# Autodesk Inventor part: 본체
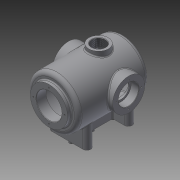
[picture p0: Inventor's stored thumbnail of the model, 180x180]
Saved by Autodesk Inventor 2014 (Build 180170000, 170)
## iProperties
Created: 2016-02
Part Number: 본체
Material: 알루미늄 6061
Document SubType Name: Modeling
Designer: mduedu
Density: 2.71 g/cm^3
Mass: 3248.02 g
Surface Area: 2109.22 cm^2
Volume: 1198.53 cm^3
Appearance: 기본값
Author: mduedu
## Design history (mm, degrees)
sketch "스케치2"
  geometry: L1 (0, 100)-(0, -100); L2 (65, -75.993)-(65, 100); L3 (65, 100)-(0, 100); A1 r 100 centre (0, 0) between (0, -100) and (65, -75.993); 2 further points
  constraints: 6 end point, 2 midpoint, 2 point on circle, 1 centre point, 1 coincident, 1 horizontal, 1 parallel, 1 vertical
  dimensions: "d3" = 200 distance of L1.start L1.end; "d5" = 130 diameter of L2 L1; "d6" = 100 radius of A1
revolve "회전1" sketch "스케치2" stored, may be unused: angle "d7" = 90 deg
sketch "스케치3"
  geometry: C1 r 47.5 at (0, 0); 1 further point
  constraints: 1 centre point, 1 coincident
  dimensions: "d8" = 95 diameter of C1
extrude "돌출2" join sketch "스케치3" distance "d10" = 10; taper "d11" = 0 deg
sketch "스케치5"
  geometry: L1 (47.5, 110)-(47.5, 100) reference; L2 (47.5, 100)-(65, 100) reference; L3 (65, 100)-(65, -75.993) reference; L4 (-65, -75.993)-(-65, 100) reference; L5 (-65, 100)-(-47.5, 100) reference; L6 (-47.5, 100)-(-47.5, 110) reference; L7 (-47.5, 110)-(47.5, 110) reference; L8 (55, 85)-(55, -71.239); L9 (0, 85)-(55, 85); L10 (0, 85)-(0, -90); A1 r 100 centre (0, 0) between (0, -100) and (65, -75.993) reference; A2 r 100 centre (0, 0) between (-65, -75.993) and (0, -100) reference; A3 r 90 centre (0, 0) between (0, -90) and (55, -71.239); 1 further point
  constraints: 6 end point, 2 point on circle, 1 centre point, 1 parallel, 1 perpendicular, 1 point on line, 1 vertical
  dimensions: "d13" = 10 distance between parallel lines of L3 L8; "d14" = 10 radial gap between concentric circles of A3 A1; "d15" = 15 distance between parallel lines of L9 L2
revolve "회전2" sketch "스케치5" stored, may be unused: angle "d16" = 90 deg
hole "구멍1" diameter "d19" = 65; stored, may be unused: countersink angle "d23" = 90 deg, drill point angle "d25" = 118 deg; dims "d17" = 10, "d18" = 10, "d20" = 6, "d21" = 4, "d22" = 2, "d24" = 8
node "작업 평면1"
sketch "스케치6"
  geometry: L1 (47.5, 110)-(-47.5, 110) reference; C1 r 41 at (0, -17); 1 further point
  constraints: 1 centre point, 1 vertical alignment
  dimensions: "d27" = 82 diameter of C1; "d29" = 127 distance from line of C1.centre L1
extrude "돌출3" join sketch "스케치6" stored distance "d30" = 10; taper "d31" = 0 deg
hole "구멍2" diameter "d34" = 42; stored, may be unused: countersink angle "d38" = 90 deg, drill point angle "d40" = 118 deg; dims "d35" = 6, "d36" = 52, "d37" = 20, "d39" = 8, "d180" = 10, "d181" = 10
sketch "스케치7" dims "d41" = 65
  geometry: C1 r 41 at (0, 0) reference; 3 further points
  constraints: 2 vertical alignment, 1 coincident, 2 other
hole "구멍3" sketch "스케치7" at (0, 32.5) diameter "d43" = 3.242; stored, may be unused: countersink angle "d47" = 90 deg, drill point angle "d49" = 118 deg; dims "d44" = 11, "d45" = 13, "d46" = 18, "d48" = 13
sketch "스케치8" dims "d53" = 80
  geometry: 3 further points
  constraints: 2 vertical alignment, 1 coincident, 2 other
hole "구멍4" sketch "스케치8" at (0, 40) diameter "d56" = 3.242; stored, may be unused: countersink angle "d60" = 90 deg, drill point angle "d62" = 118 deg; dims "d57" = 11, "d58" = 13, "d59" = 18, "d61" = 13
fillet "모깎기1" dims "d66" = 10
fillet "모깎기2" dims "d67" = 3
fillet "모깎기3" dims "d68" = 0.3
chamfer "모따기1" distance "d69" = 1; stored, may be unused: second distance "d70" = 2, angle "d71" = 45 deg
node "작업 평면5"
sketch "스케치10"
  geometry: L1 (-50, -63)-(50, -63); L2 (50, -63)-(50, -43); L3 (50, -43)-(-50, -43); L4 (-50, -43)-(-50, -63); L5 (-50, 0)-(50, 0); L6 (-50, 63)-(50, 63); L7 (50, 63)-(50, 43); L8 (50, 43)-(-50, 43); L9 (-50, 43)-(-50, 63); 2 further points
  constraints: 18 end point, 4 symmetric about line, 2 parallel, 2 perpendicular, 1 coincident, 1 horizontal, 1 midpoint
  dimensions: "d80" = 20 distance of L3.end L1.start; "d82" = 100 distance of L1.start L1.end; "d130" = 43 vertical distance of L3.end point (0, 0); "d131" = 50 horizontal distance of L3.end point (0, 0); "d132" = 100 distance of L5.start L5.end
extrude "돌출5" join sketch "스케치10" stored distance "d84" = 10; taper "d85" = 0 deg
sketch "스케치11"
  geometry: L1 (-100, -43)-(-100, 43); L2 (-65, 90)-(-65, -71.239) reference; L3 (-100, -43)-(-41.533, -43) reference; L4 (-100, 43)-(-41.533, 43) reference; 1 further point
  constraints: 2 end point, 1 point on line, 1 vertical
feature "리브1" sketch "스케치11" dims "d88" = 1, "d89" = 20, "d90" = 0, "d91" = 0, "d92" = 1, "d93" = 1
fillet "모깎기12"
fillet "모깎기13"
fillet "모깎기14"
fillet "모깎기15"
fillet "모깎기16" dims "d167" = 3
fillet "모깎기17" dims "d168" = 3
node "작업 평면6"
sketch "스케치19"
  geometry: L1 (77, -58)-(77, 24) reference; L2 (-77, -58)-(-77, 24) reference; L3 (77, -17)-(-77, -17); C1 r 25 at (0, -17); 1 further point
  constraints: 3 midpoint, 2 end point, 1 centre point
  dimensions: "d149" = 50 diameter of C1
extrude "돌출11" join sketch "스케치19" stored distance "d150" = 10; taper "d151" = 0 deg
hole "구멍6" diameter "d154" = 35; stored, may be unused: countersink angle "d158" = 90 deg, drill point angle "d160" = 118 deg; dims "d152" = 10, "d153" = 10, "d155" = 6, "d156" = 4, "d157" = 2, "d159" = 8
fillet "모깎기11" dims "d161" = 3
feature "스레드1" dims "d162" = 10, "d163" = 0
chamfer "모따기3" distance "d164" = 1; stored, may be unused: second distance "d165" = 2, angle "d166" = 45 deg
sketch "스케치20"
  geometry: L1 (10, 40)-(10, -40) reference; L2 (13, -43)-(40, -43) reference; L3 (40, -63)-(-40, -63) reference; L4 (-40, -43)-(-13, -43) reference; L5 (-10, -40)-(-10, 40) reference; L6 (-13, 43)-(-40, 43) reference; L7 (-40, 63)-(40, 63) reference; L8 (40, 43)-(13, 43) reference; L9 (-40, 53)-(40, 53); L10 (-40, -53)-(40, -53); L11 (0, 53)-(0, -53); C1 r 5 at (0, 53); C2 r 5 at (0, 0); C3 r 5 at (0, -53); A1 r 3 centre (13, -40) between (10, -40) and (13, -43) reference; A2 r 10 centre (40, -53) between (40, -63) and (40, -43) reference; A3 r 10 centre (-40, -53) between (-40, -43) and (-40, -63) reference; A4 r 3 centre (-13, -40) between (-13, -43) and (-10, -40) reference; A5 r 3 centre (-13, 40) between (-10, 40) and (-13, 43) reference; A6 r 10 centre (-40, 53) between (-40, 63) and (-40, 43) reference; A7 r 10 centre (40, 53) between (40, 43) and (40, 63) reference; A8 r 3 centre (13, 40) between (13, 43) and (10, 40) reference; 1 further point
  constraints: 6 end point, 3 centre point, 3 coincident, 2 midpoint, 2 parallel
  dimensions: "d169" = 10 diameter of C1; "d170" = 10 diameter of C2; "d171" = 10 diameter of C3
extrude "돌출12" join sketch "스케치20" distance "d172" = 10; taper "d173" = 0 deg
chamfer "모따기4" distance "d174" = 1; stored, may be unused: second distance "d175" = 2, angle "d176" = 45 deg
node "솔리드2"
pattern_circular "원형 패턴1" dims angle "d51" = 360 deg
mirror "대칭1"
pattern_circular "원형 패턴2" dims angle "d64" = 360 deg
node "절단 모서리 투영1"
node "절단 모서리 투영4"
other parameters: "d26" = 77, "d136" = 175
